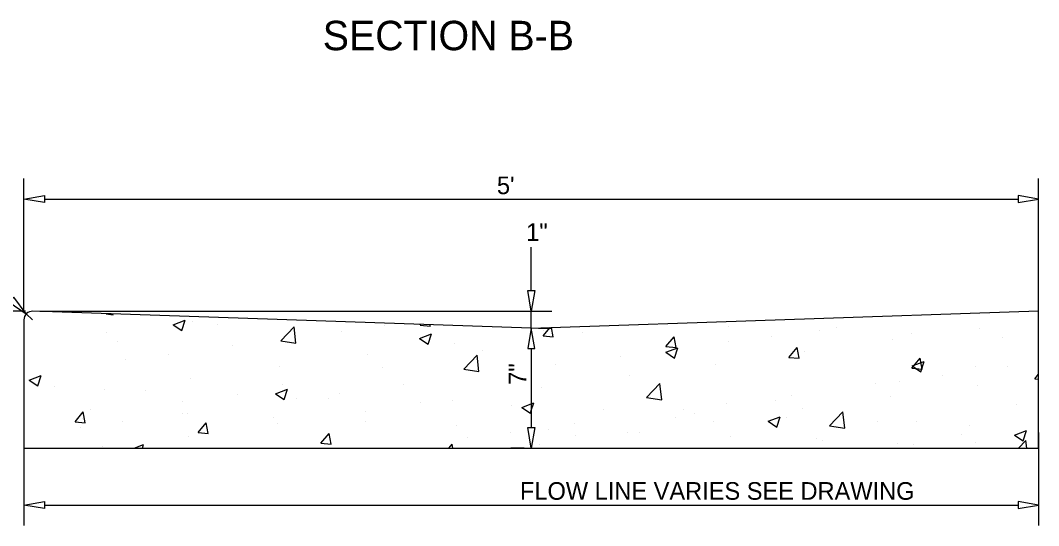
# Model space of a CAD drawing. Extents: x 6712067 to 6713867, y 1867712 to 1869162.
# Drawn here: x 6712266.7 to 6712613.1, y 1868388.6 to 1868560.4 of the extents above; entities that cross this region are included whole.
import ezdxf

# ---------------------------------------------------------------- set-up
doc = ezdxf.new("R2010")
doc.units = 0
for name, color, linetype in [('Control (1)', 7, 'Continuous'), ('G-MARK', 7, 'Continuous'), ('G-TEXT', 7, 'Continuous'), ('Misc CnstDet(22)', 7, 'Continuous')]:
    doc.layers.add(name, color=color, linetype=linetype)

msp = doc.modelspace()

# ---------------------------------------------------------------- linework, layer by layer
at = {"layer": 'Control (1)'}
msp.add_line((6712613.07, 1868499.65), (6712613.07, 1868499.65), dxfattribs=at)
at = {"layer": 'G-MARK'}
for p, q in [((6712267.98, 1868461.05), (6712267.98, 1868506.65)), ((6712613.07, 1868461.05), (6712613.07, 1868506.65)), ((6712274.96, 1868499.65), (6712606.1, 1868499.65)), ((6712440.53, 1868468.51), (6712440.53, 1868483.33)), ((6712268.44, 1868461.51), (6712245.53, 1868461.51)), ((6712273.33, 1868461.51), (6712447.53, 1868461.51)), ((6712440.53, 1868455.79), (6712440.53, 1868461.51)), ((6712440.53, 1868448.79), (6712440.53, 1868421.96)), ((6712267.98, 1868420.24), (6712267.98, 1868388.59)), ((6712613.07, 1868420.24), (6712613.07, 1868388.59)), ((6712274.96, 1868395.59), (6712606.1, 1868395.59))]:
    msp.add_line(p, q, dxfattribs=at)
at = {"layer": 'G-TEXT'}
for points in [[(6712274.96, 1868500.82), (6712274.96, 1868498.48), (6712267.98, 1868499.65)], [(6712606.1, 1868500.82), (6712606.1, 1868498.48), (6712613.07, 1868499.65)], [(6712439.36, 1868468.51), (6712441.7, 1868468.51), (6712440.53, 1868461.51)], [(6712264.49, 1868466.26), (6712262.89, 1868464.56), (6712268.76, 1868460.59)], [(6712439.36, 1868448.79), (6712441.7, 1868448.79), (6712440.53, 1868455.79)], [(6712439.36, 1868421.96), (6712441.7, 1868421.96), (6712440.53, 1868414.98)], [(6712274.96, 1868396.76), (6712274.96, 1868394.42), (6712267.98, 1868395.59)], [(6712606.1, 1868396.76), (6712606.1, 1868394.42), (6712613.07, 1868395.59)]]:
    msp.add_lwpolyline(points, close=True, dxfattribs=at)
at = {"layer": 'Misc CnstDet(22)'}
for p, q in [((6712270.9, 1868461.51), (6712270.9, 1868461.51)), ((6712270.9, 1868461.51), (6712270.9, 1868461.51)), ((6712440.52, 1868455.78), (6712270.98, 1868461.49)), ((6712440.52, 1868455.78), (6712613.07, 1868461.61)), ((6712613.07, 1868414.97), (6712613.07, 1868461.61)), ((6712267.98, 1868458.59), (6712267.98, 1868458.59)), ((6712267.98, 1868458.58), (6712267.98, 1868414.97)), ((6712270.9, 1868458.59), (6712268.76, 1868460.59)), ((6712268.76, 1868460.59), (6712268.76, 1868460.59)), ((6712270.9, 1868458.59), (6712270.9, 1868458.59)), ((6712295.95, 1868460.64), (6712298.29, 1868460.3)), ((6712298.29, 1868460.3), (6712298.25, 1868460.58)), ((6712318.74, 1868456.88), (6712322.83, 1868458.44)), ((6712321.63, 1868454.91), (6712322.83, 1868458.44)), ((6712613.07, 1868458.59), (6712613.07, 1868458.59)), ((6712318.74, 1868456.88), (6712321.66, 1868454.93)), ((6712325.38, 1868457.87), (6712325.38, 1868457.87)), ((6712333.75, 1868457.02), (6712333.75, 1868457.02)), ((6712355.33, 1868451.44), (6712359.85, 1868456.17)), ((6712360.49, 1868450.64), (6712359.85, 1868456.17)), ((6712375.87, 1868454.7), (6712375.87, 1868454.7)), ((6712390.46, 1868456.63), (6712390.46, 1868456.63)), ((6712402.7, 1868456.79), (6712402.9, 1868457.04)), ((6712402.7, 1868456.79), (6712406.19, 1868456.47)), ((6712406.16, 1868456.47), (6712406.09, 1868456.93)), ((6712440.53, 1868455.79), (6712440.53, 1868455.79)), ((6712440.53, 1868455.79), (6712440.53, 1868455.79)), ((6712440.53, 1868455.79), (6712440.53, 1868455.79)), ((6712442.98, 1868455.79), (6712447.53, 1868455.79)), ((6712442.98, 1868455.79), (6712447.53, 1868455.79)), ((6712444.51, 1868453.12), (6712446.9, 1868455.99)), ((6712444.61, 1868455.04), (6712444.61, 1868455.04)), ((6712447.98, 1868452.82), (6712447.41, 1868456.01)), ((6712507.49, 1868456.42), (6712507.49, 1868456.42)), ((6712538.61, 1868455.11), (6712538.61, 1868455.11)), ((6712544.19, 1868455.89), (6712544.19, 1868455.89)), ((6712592.94, 1868455.69), (6712592.94, 1868455.69)), ((6712295.93, 1868454.15), (6712295.93, 1868454.15)), ((6712299.74, 1868451.19), (6712299.74, 1868451.19)), ((6712355.33, 1868451.44), (6712360.49, 1868450.64)), ((6712402.51, 1868452.2), (6712406.6, 1868453.78)), ((6712402.51, 1868452.2), (6712405.43, 1868450.25)), ((6712405.43, 1868450.25), (6712406.6, 1868453.78)), ((6712444.51, 1868453.12), (6712447.98, 1868452.82)), ((6712458.01, 1868454.13), (6712458.01, 1868454.13)), ((6712486.31, 1868449.47), (6712489.13, 1868452.82)), ((6712489.8, 1868449.15), (6712489.13, 1868452.82)), ((6712522.11, 1868452.98), (6712522.11, 1868452.98)), ((6712563.49, 1868451.95), (6712563.49, 1868451.95)), ((6712569.74, 1868453.78), (6712569.74, 1868453.78)), ((6712600.86, 1868452.47), (6712600.86, 1868452.47)), ((6712339.05, 1868449.86), (6712339.05, 1868449.86)), ((6712414.33, 1868450.68), (6712414.33, 1868450.68)), ((6712424, 1868448.3), (6712424, 1868448.3)), ((6712440.53, 1868448.79), (6712440.53, 1868441.79)), ((6712486.31, 1868449.47), (6712489.8, 1868449.17)), ((6712486.31, 1868447.54), (6712490.39, 1868449.1)), ((6712489.2, 1868445.59), (6712490.39, 1868449.1)), ((6712507.51, 1868451.05), (6712507.51, 1868451.05)), ((6712528.12, 1868445.8), (6712530.95, 1868449.15)), ((6712531.61, 1868445.5), (6712530.95, 1868449.15)), ((6712533.56, 1868447.86), (6712533.56, 1868447.86)), ((6712302.38, 1868445.01), (6712302.38, 1868445.01)), ((6712316.98, 1868446.94), (6712316.98, 1868446.94)), ((6712384.89, 1868446.94), (6712384.89, 1868446.94)), ((6712417.52, 1868441.8), (6712422.07, 1868446.53)), ((6712422.71, 1868441), (6712422.07, 1868446.53)), ((6712470.7, 1868446.21), (6712470.7, 1868446.21)), ((6712486.31, 1868447.54), (6712489.2, 1868445.59)), ((6712528.12, 1868445.8), (6712531.61, 1868445.5)), ((6712569.94, 1868442.15), (6712572.76, 1868445.5)), ((6712570.08, 1868442.88), (6712574.16, 1868444.44)), ((6712573.43, 1868441.85), (6712572.74, 1868445.5)), ((6712572.97, 1868440.91), (6712574.16, 1868444.44)), ((6712354.96, 1868442.83), (6712354.96, 1868442.83)), ((6712390.01, 1868442.44), (6712390.01, 1868442.44)), ((6712417.52, 1868441.8), (6712422.71, 1868441)), ((6712434.03, 1868441.39), (6712434.03, 1868441.39)), ((6712448.62, 1868443.29), (6712448.62, 1868443.29)), ((6712503.27, 1868443.48), (6712503.27, 1868443.48)), ((6712569.94, 1868442.15), (6712573.43, 1868441.85)), ((6712570.08, 1868442.88), (6712572.97, 1868440.91)), ((6712591.58, 1868442.67), (6712591.58, 1868442.67)), ((6712602.35, 1868442.56), (6712602.35, 1868442.56)), ((6712269.77, 1868438.08), (6712273.85, 1868439.64)), ((6712269.77, 1868438.08), (6712272.66, 1868436.11)), ((6712272.66, 1868436.11), (6712273.85, 1868439.64)), ((6712324.66, 1868438.47), (6712324.66, 1868438.47)), ((6712473.82, 1868439.74), (6712473.82, 1868439.74)), ((6712565.67, 1868437.74), (6712565.67, 1868437.74)), ((6712580.27, 1868439.67), (6712580.27, 1868439.67)), ((6712611.76, 1868438.5), (6712613.07, 1868440.06)), ((6712611.76, 1868438.5), (6712613.07, 1868438.38)), ((6712278.33, 1868435.83), (6712278.33, 1868435.83)), ((6712295.24, 1868434.73), (6712295.24, 1868434.73)), ((6712309.42, 1868434.53), (6712309.42, 1868434.53)), ((6712353.54, 1868433.4), (6712357.62, 1868434.96)), ((6712356.02, 1868436.61), (6712356.02, 1868436.61)), ((6712356.45, 1868431.45), (6712357.62, 1868434.96)), ((6712397.21, 1868436.55), (6712397.21, 1868436.55)), ((6712443.89, 1868435.65), (6712443.89, 1868435.65)), ((6712479.74, 1868432.14), (6712484.29, 1868436.89)), ((6712484.93, 1868431.34), (6712484.29, 1868436.87)), ((6712557.59, 1868436.84), (6712557.59, 1868436.84)), ((6712592.23, 1868436.27), (6712592.23, 1868436.27)), ((6712322, 1868430.79), (6712322, 1868430.79)), ((6712340.55, 1868433.22), (6712340.55, 1868433.22)), ((6712353.54, 1868433.4), (6712356.45, 1868431.45)), ((6712360.54, 1868431.7), (6712360.54, 1868431.7)), ((6712371.67, 1868431.89), (6712371.67, 1868431.89)), ((6712375.13, 1868433.63), (6712375.13, 1868433.63)), ((6712402.79, 1868430.58), (6712402.79, 1868430.58)), ((6712413.62, 1868431.27), (6712413.62, 1868431.27)), ((6712440.52, 1868427.69), (6712441.39, 1868430.3)), ((6712440.52, 1868429.96), (6712441.39, 1868430.3)), ((6712479.74, 1868432.14), (6712484.93, 1868431.34)), ((6712523.58, 1868431.01), (6712523.58, 1868431.01)), ((6712528.86, 1868432.9), (6712528.86, 1868432.9)), ((6712562.78, 1868432.55), (6712562.78, 1868432.55)), ((6712285.35, 1868423.9), (6712288.15, 1868427.25)), ((6712288.81, 1868423.6), (6712288.15, 1868427.25)), ((6712290.61, 1868428.01), (6712290.61, 1868428.01)), ((6712323.72, 1868426.86), (6712323.72, 1868426.86)), ((6712384.18, 1868427.55), (6712384.18, 1868427.55)), ((6712433.91, 1868429.27), (6712433.91, 1868429.27)), ((6712437.33, 1868428.74), (6712440.52, 1868429.96)), ((6712437.33, 1868428.74), (6712440.22, 1868426.79)), ((6712440.22, 1868426.77), (6712440.52, 1868427.69)), ((6712465.03, 1868427.94), (6712465.03, 1868427.94)), ((6712492.18, 1868428.05), (6712492.18, 1868428.05)), ((6712506.78, 1868429.98), (6712506.78, 1868429.98)), ((6712532.85, 1868428.44), (6712532.85, 1868428.44)), ((6712541.96, 1868422.5), (6712546.51, 1868427.23)), ((6712547.15, 1868421.7), (6712546.51, 1868427.23)), ((6712605.54, 1868429.89), (6712605.54, 1868429.89)), ((6712285.35, 1868423.9), (6712288.81, 1868423.6)), ((6712288.01, 1868424.96), (6712288.01, 1868424.96)), ((6712301.64, 1868423.95), (6712301.64, 1868423.95)), ((6712321.73, 1868426.7), (6712321.73, 1868426.7)), ((6712327.17, 1868420.25), (6712329.97, 1868423.6)), ((6712330.63, 1868419.93), (6712329.97, 1868423.6)), ((6712352.85, 1868425.37), (6712352.85, 1868425.37)), ((6712354.25, 1868423.44), (6712354.25, 1868423.44)), ((6712383.97, 1868424.06), (6712383.97, 1868424.06)), ((6712489.59, 1868425.19), (6712489.59, 1868425.19)), ((6712496.15, 1868426.63), (6712496.15, 1868426.63)), ((6712502.56, 1868424.08), (6712502.56, 1868424.08)), ((6712521.1, 1868424.06), (6712525.19, 1868425.64)), ((6712521.1, 1868424.06), (6712523.99, 1868422.11)), ((6712523.99, 1868422.11), (6712525.19, 1868425.62)), ((6712527.28, 1868425.32), (6712527.28, 1868425.32)), ((6712558.4, 1868424.01), (6712558.4, 1868424.01)), ((6712571.55, 1868424.04), (6712571.55, 1868424.04)), ((6712267.98, 1868422.7), (6712267.98, 1868422.7)), ((6712287.05, 1868422.04), (6712287.05, 1868422.04)), ((6712327.17, 1868420.25), (6712330.63, 1868419.95)), ((6712368.96, 1868416.58), (6712371.78, 1868419.93)), ((6712372.45, 1868416.28), (6712371.78, 1868419.93)), ((6712415.09, 1868422.75), (6712415.09, 1868422.75)), ((6712433.29, 1868420.32), (6712433.29, 1868420.32)), ((6712446.21, 1868421.44), (6712446.21, 1868421.44)), ((6712455.37, 1868423.21), (6712455.37, 1868423.21)), ((6712473.11, 1868420.34), (6712473.11, 1868420.34)), ((6712477.33, 1868420.11), (6712477.33, 1868420.11)), ((6712541.96, 1868422.5), (6712547.15, 1868421.7)), ((6712589.52, 1868422.68), (6712589.52, 1868422.68)), ((6712604.87, 1868419.4), (6712608.96, 1868420.96)), ((6712607.76, 1868417.45), (6712608.96, 1868420.96)), ((6712613.07, 1868422.7), (6712613.07, 1868422.7)), ((6712323.98, 1868419.06), (6712323.98, 1868419.06)), ((6712368.96, 1868416.58), (6712372.45, 1868416.28)), ((6712418.69, 1868418.39), (6712418.69, 1868418.39)), ((6712455.6, 1868419.33), (6712455.6, 1868419.33)), ((6712508.43, 1868418.8), (6712508.43, 1868418.8)), ((6712537.56, 1868418.21), (6712537.56, 1868418.21)), ((6712539.55, 1868417.5), (6712539.55, 1868417.5)), ((6712564.94, 1868416.67), (6712564.94, 1868416.67)), ((6712586.99, 1868419.59), (6712586.99, 1868419.59)), ((6712591.52, 1868416.88), (6712591.52, 1868416.88)), ((6712604.87, 1868419.4), (6712607.79, 1868417.45)), ((6712606.2, 1868414.97), (6712608.73, 1868417.59)), ((6712609.03, 1868414.97), (6712608.71, 1868417.59)), ((6712267.98, 1868414.98), (6712267.98, 1868414.98)), ((6712267.98, 1868414.97), (6712613.07, 1868414.97)), ((6712294.53, 1868415.34), (6712294.53, 1868415.34)), ((6712305.5, 1868414.97), (6712308.64, 1868416.17)), ((6712308.23, 1868414.97), (6712308.64, 1868416.17)), ((6712412.47, 1868414.97), (6712413.6, 1868416.28)), ((6712413.83, 1868414.97), (6712413.6, 1868416.28)), ((6712438.07, 1868414.98), (6712433.53, 1868414.98)), ((6712440.53, 1868414.98), (6712440.53, 1868414.98)), ((6712440.53, 1868414.98), (6712440.53, 1868414.98)), ((6712443.18, 1868416.23), (6712443.18, 1868416.23)), ((6712570.68, 1868416.17), (6712570.68, 1868416.17)), ((6712613.07, 1868395.59), (6712613.07, 1868395.59))]:
    msp.add_line(p, q, dxfattribs=at)
msp.add_lwpolyline([(6712439.36, 1868448.79), (6712441.7, 1868448.79), (6712440.53, 1868455.79)], close=True, dxfattribs=at)
msp.add_arc((6712270.88, 1868458.58), 2.91, 88.0651, 180, dxfattribs=at)

# ---------------------------------------------------------------- texts
for s, height, p in [('SECTION B-B', 10, (6712369.59, 1868550.25)), ("5'", 6, (6712428.83, 1868501.3)), ('FLOW LINE VARIES SEE DRAWING', 6, (6712436.67, 1868397.38))]:
    msp.add_text(s, height=height, dxfattribs=at).set_placement(p)
for s, rotation, p in [('1"', 0.01, (6712438.79, 1868485.42)), ('7"', 90, (6712438.87, 1868436.47))]:
    msp.add_text(s, height=6, rotation=rotation, dxfattribs=at).set_placement(p)

doc.saveas('drawing.dxf')
